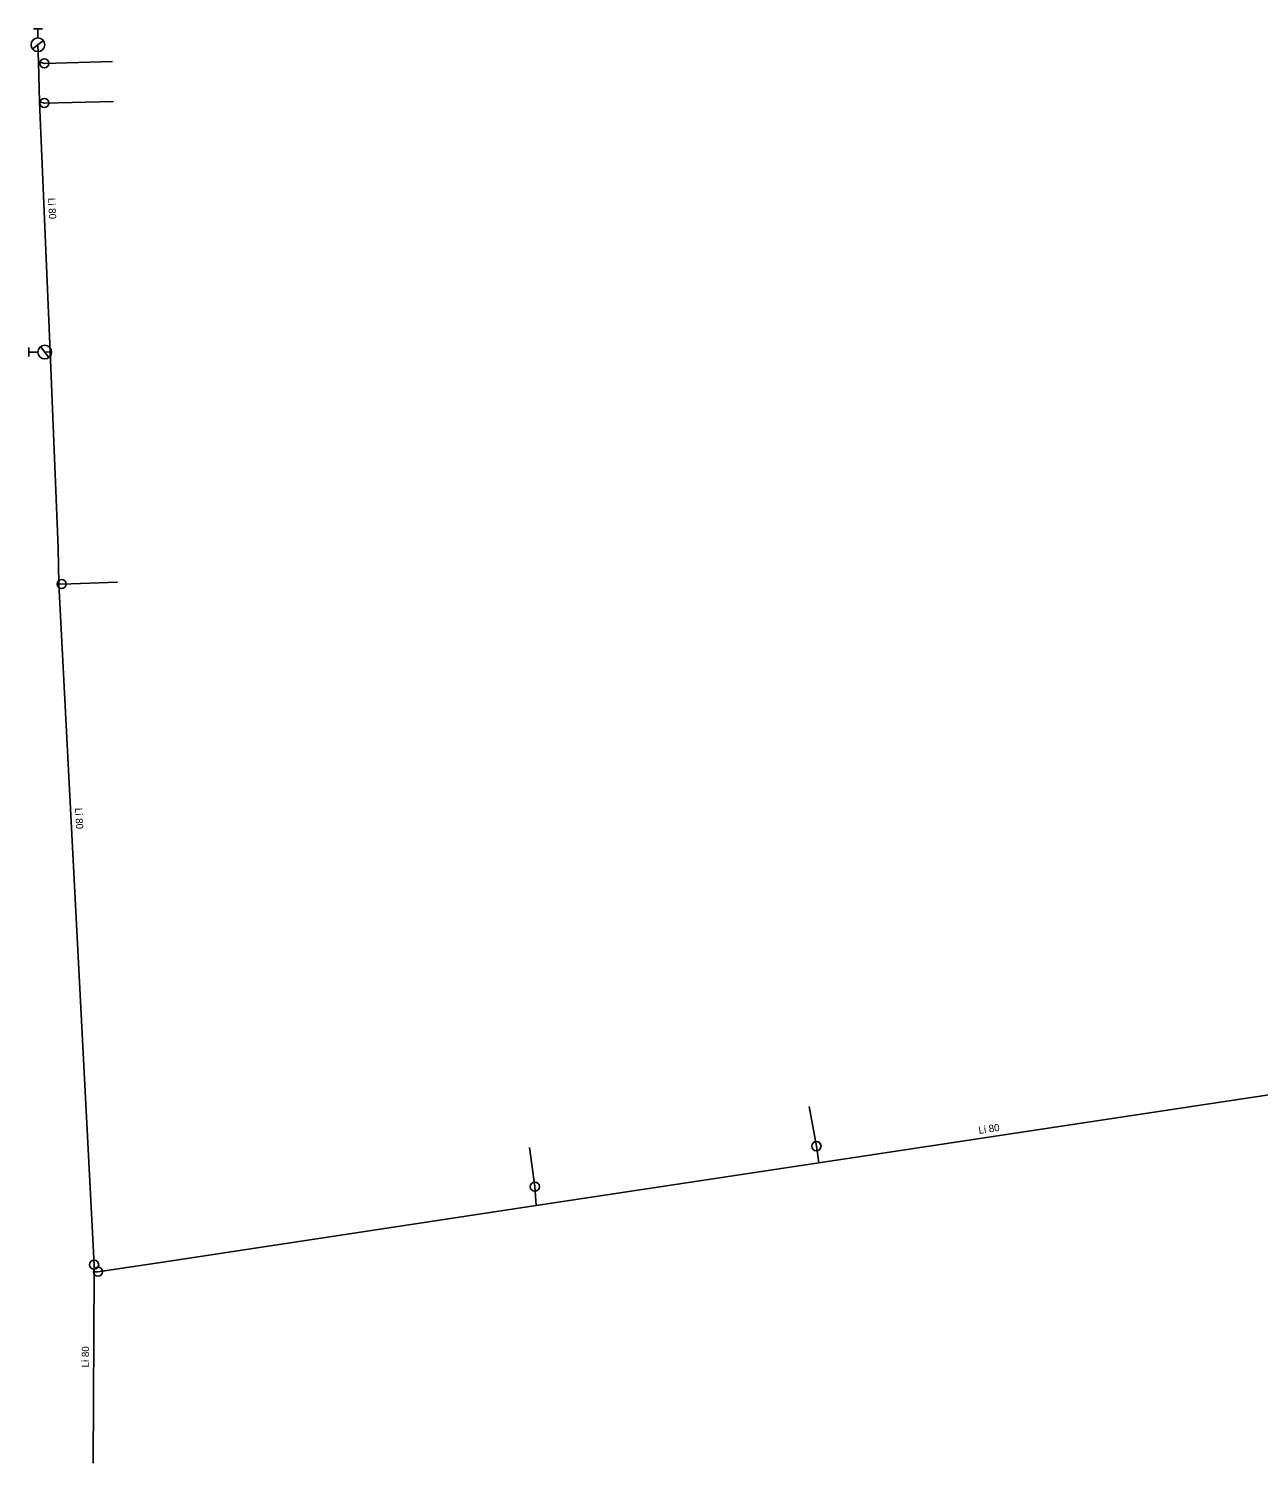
# Model space of a CAD drawing. Extents: x -783658 to -783200, y -1065250 to -1064865.
# Drawn here: x -783337.2 to -783270, y -1065243.8 to -1065165.4 of the extents above; entities that cross this region are included whole.
import ezdxf

# ---------------------------------------------------------------- set-up
doc = ezdxf.new("R2010")
doc.units = 0
for name, color, linetype in [('Hydranty', 7, 'Continuous'), ('Popis vodovodních řadů', 7, 'Continuous'), ('Vod přípojky-voda pitná', 7, 'Continuous'), ('Vodovodní řad', 7, 'Continuous'), ('Vodovodní šoupata', 7, 'Continuous')]:
    doc.layers.add(name, color=color, linetype=linetype)

msp = doc.modelspace()

# ---------------------------------------------------------------- linework, layer by layer
at = {"layer": 'Hydranty'}
for p, q in [((-783336.92, -1065165.405), (-783336.42, -1065165.405)), ((-783336.67, -1065165.905), (-783336.67, -1065165.405)), ((-783336.964, -1065166.511), (-783336.374, -1065166.048)), ((-783337.175, -1065183.33), (-783337.175, -1065182.83)), ((-783336.675, -1065183.08), (-783337.175, -1065183.08)), ((-783336.069, -1065183.374), (-783336.532, -1065182.784))]:
    msp.add_line(p, q, dxfattribs=at)
for centre in [(-783336.67, -1065166.28), (-783336.3, -1065183.08)]:
    msp.add_circle(centre, 0.375, dxfattribs=at)
at = {"layer": 'Vod přípojky-voda pitná'}
for points in [[(-783336.64, -1065167.22), (-783336.32, -1065167.3), (-783332.59, -1065167.2)], [(-783336.59, -1065169.41), (-783336.32, -1065169.47), (-783332.54, -1065169.39)], [(-783335.53, -1065195.75), (-783335.37, -1065195.76), (-783332.33, -1065195.65)], [(-783293.99, -1065227.4), (-783294.12, -1065226.49), (-783294.51, -1065224.32)], [(-783309.43, -1065229.73), (-783309.51, -1065228.7), (-783309.8, -1065226.57)]]:
    msp.add_lwpolyline(points, dxfattribs=at)
at = {"layer": 'Vodovodní řad'}
for points in [[(-783336, -1065183.06), (-783336.59, -1065169.41), (-783336.64, -1065167.22), (-783336.67, -1065166.28)], [(-783336, -1065183.06), (-783336.3, -1065183.08)], [(-783333.6, -1065232.97), (-783335.53, -1065195.75), (-783335.56, -1065193.78), (-783336, -1065183.06)], [(-783329.85, -1065232.82), (-783309.43, -1065229.73), (-783293.99, -1065227.4), (-783258.67, -1065222.06), (-783242.23, -1065221.98), (-783240.34, -1065221.84)], [(-783333.6, -1065233.35), (-783333.6, -1065232.97)], [(-783333.39, -1065233.35), (-783329.85, -1065232.82)], [(-783333.66, -1065243.824), (-783333.6, -1065233.35)], [(-783333.6, -1065233.35), (-783333.39, -1065233.35)]]:
    msp.add_lwpolyline(points, dxfattribs=at)
at = {"layer": 'Vodovodní šoupata'}
for centre in [(-783336.32, -1065167.3), (-783336.32, -1065169.47), (-783335.37, -1065195.76), (-783294.12, -1065226.49), (-783309.51, -1065228.7), (-783333.6, -1065232.97), (-783333.39, -1065233.35)]:
    msp.add_circle(centre, 0.25, dxfattribs=at)

# ---------------------------------------------------------------- texts
at = {"layer": 'Popis vodovodních řadů'}
for rotation, p in [(272.47498, (-783336.113, -1065174.66)), (272.96835, (-783334.644, -1065208.006)), (8.59739, (-783285.233, -1065225.823)), (89.67178, (-783333.88, -1065238.585))]:
    msp.add_text('Li 80', height=0.4, rotation=rotation, dxfattribs=at).set_placement(p)

doc.saveas('drawing.dxf')
